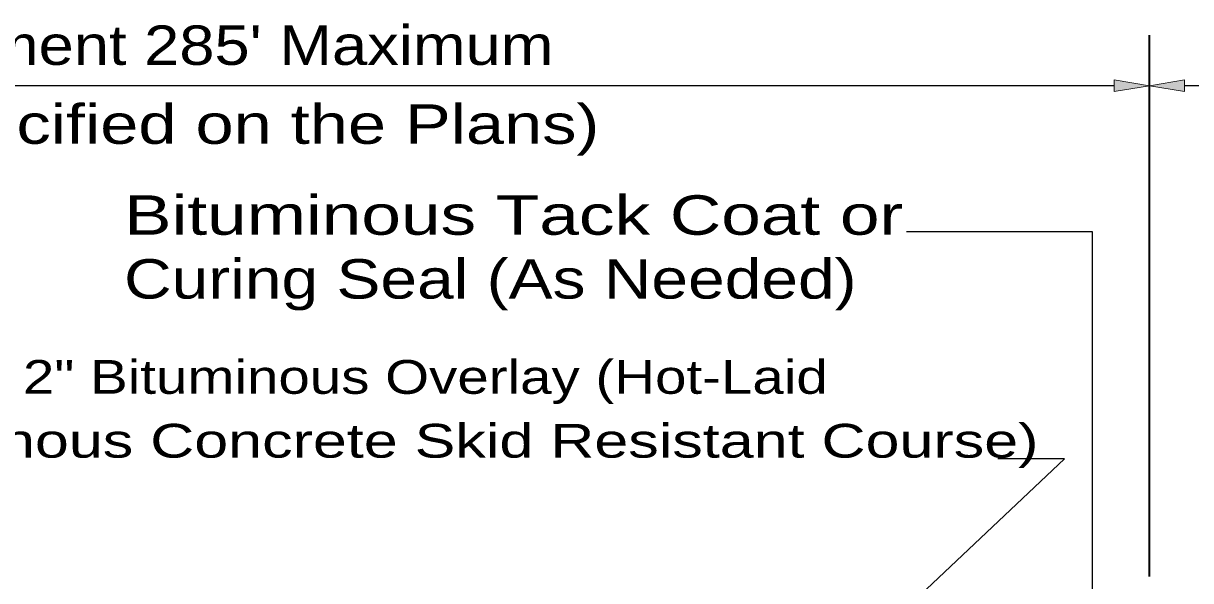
# Model space of a CAD drawing. Extents: x 36.4 to 71.7, y 0.5 to 22.5.
# Drawn here: x 53.788 to 57.934, y 10.222 to 12.2 of the extents above; entities that cross this region are included whole.
import ezdxf

# ---------------------------------------------------------------- set-up
doc = ezdxf.new("R2010")
doc.units = 0
doc.header["$LTSCALE"] = 0.056
doc.layers.add('1', color=7, linetype='Continuous', lineweight=40)
doc.layers.add('3', color=7, linetype='Continuous', lineweight=13)

msp = doc.modelspace()

# ---------------------------------------------------------------- hatches: boundary and pattern name
at = {"layer": '1'}
msp.add_hatch(color=256, dxfattribs=at).paths.add_polyline_path([(57.66217, 11.95783), (57.66217, 11.9995), (57.78717, 11.97867), (57.78717, 11.97867)])
at = {"layer": '3'}
msp.add_hatch(color=256, dxfattribs=at).paths.add_polyline_path([(57.91217, 11.95783), (57.91217, 11.9995), (57.78717, 11.97867), (57.78717, 11.97867)])

# ---------------------------------------------------------------- linework, layer by layer
at = {"layer": '1', "lineweight": 35}
msp.add_line((57.78717, 10.23658), (57.78717, 12.15867), dxfattribs=at)
at = {"layer": '1', "lineweight": 25}
msp.add_line((57.66217, 11.97867), (48.14858, 11.97867), dxfattribs=at)
at = {"layer": '1', "lineweight": 13}
msp.add_lwpolyline([(57.66217, 11.95783), (57.66217, 11.9995), (57.78717, 11.97867), (57.78717, 11.97867)], close=True, dxfattribs=at)
at = {"layer": '3'}
for p, q in [((57.78717, 10.23658), (57.78717, 12.15867)), ((57.78717, 11.97867), (57.78725, 11.97867))]:
    msp.add_line(p, q, dxfattribs=at)
at = {"layer": '3', "lineweight": 25}
msp.add_line((59.73708, 11.97867), (57.91217, 11.97867), dxfattribs=at)
at = {"layer": '3'}
msp.add_lwpolyline([(57.91217, 11.95783), (57.91217, 11.9995), (57.78717, 11.97867), (57.78717, 11.97867)], close=True, dxfattribs=at)
at = {"layer": '3', "lineweight": 25}
for points in [[(57.58467, 10.08658), (57.58467, 11.46008), (56.92442, 11.46008)], [(56.99567, 10.19183), (57.486, 10.65383), (57.2495, 10.65383)]]:
    msp.add_lwpolyline(points, dxfattribs=at)

# ---------------------------------------------------------------- texts
at = {"layer": '3'}
for s, height, width, p in [("Concrete Bridge Transition Pavement 285' Maximum", 0.14, 1.2, (50.40867, 12.05283)), ('(Total Length as Shown or Specified on the Plans)', 0.14, 1.3, (50.40867, 11.77258)), ('Bituminous Tack Coat or', 0.14, 1.35, (54.14592, 11.44975)), ('Curing Seal (As Needed)', 0.14, 1.25, (54.14592, 11.22308)), ('2" Bituminous Overlay (Hot-Laid', 0.12, 1.25, (53.78675, 10.885)), ('Bituminous Concrete Skid Resistant Course)', 0.12, 1.35, (53.107, 10.65833))]:
    msp.add_text(s, height=height, dxfattribs=dict(at, width=width)).set_placement(p)

doc.saveas('drawing.dxf')
